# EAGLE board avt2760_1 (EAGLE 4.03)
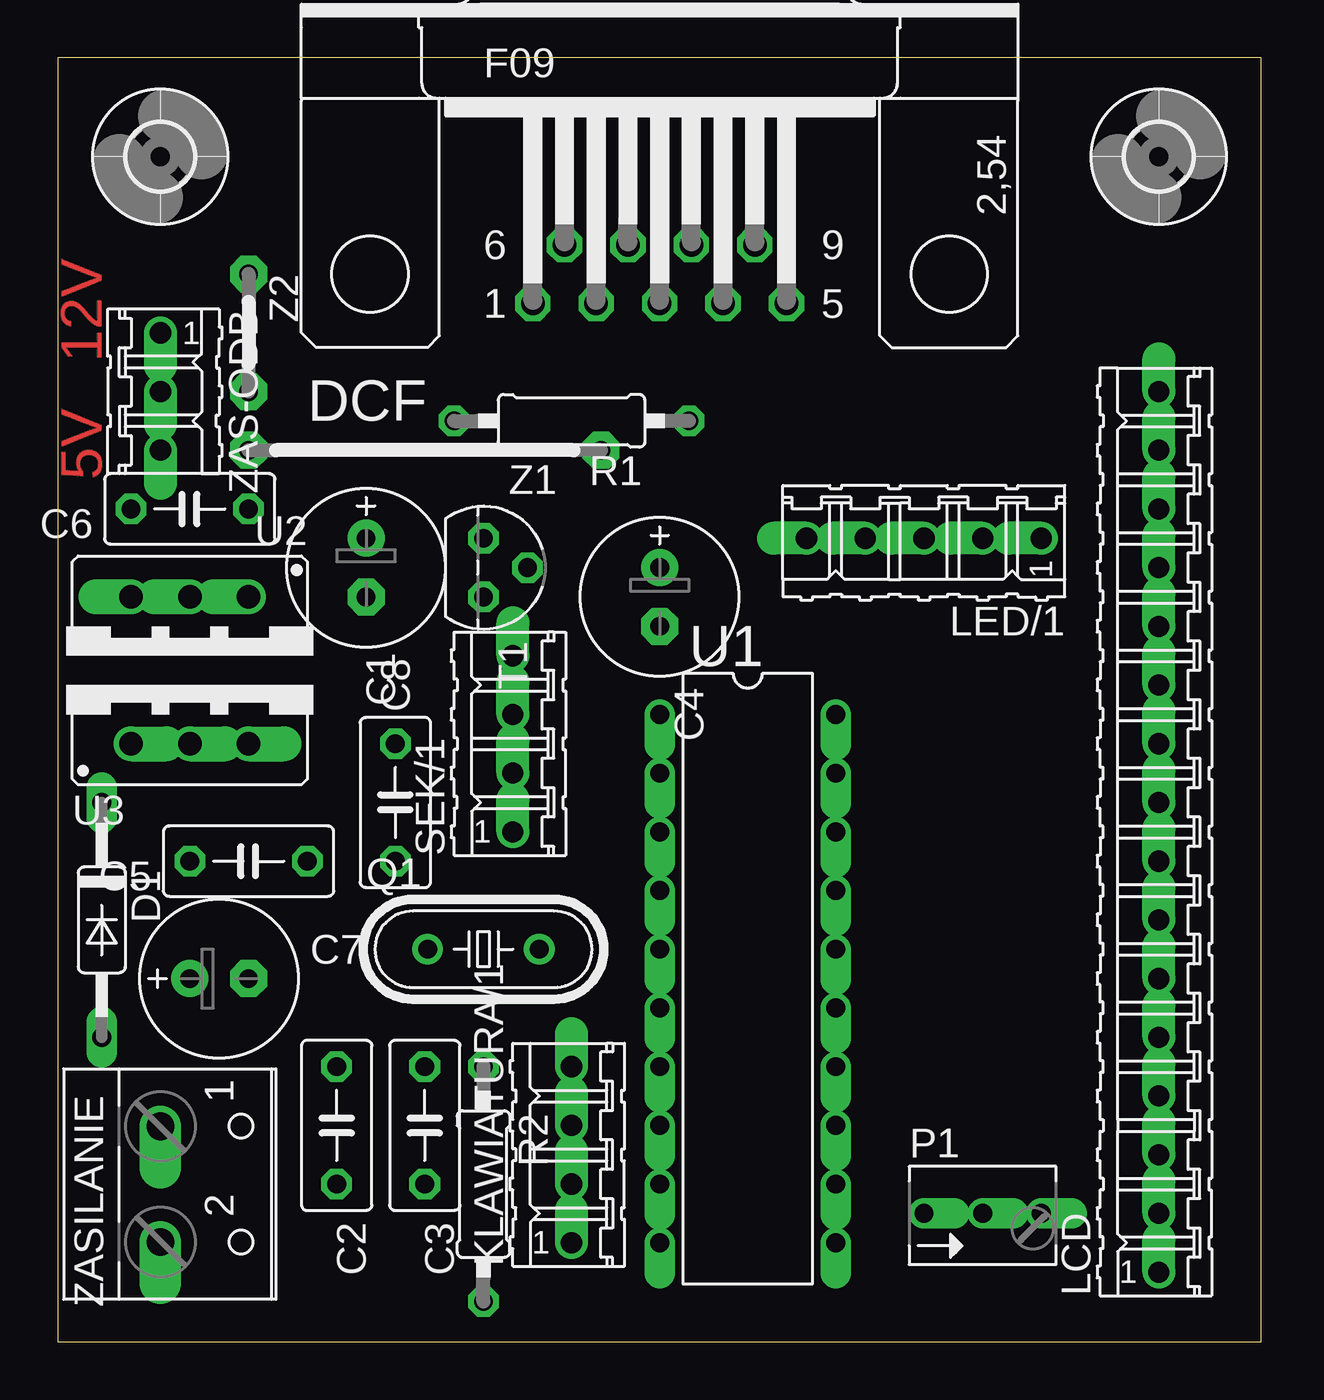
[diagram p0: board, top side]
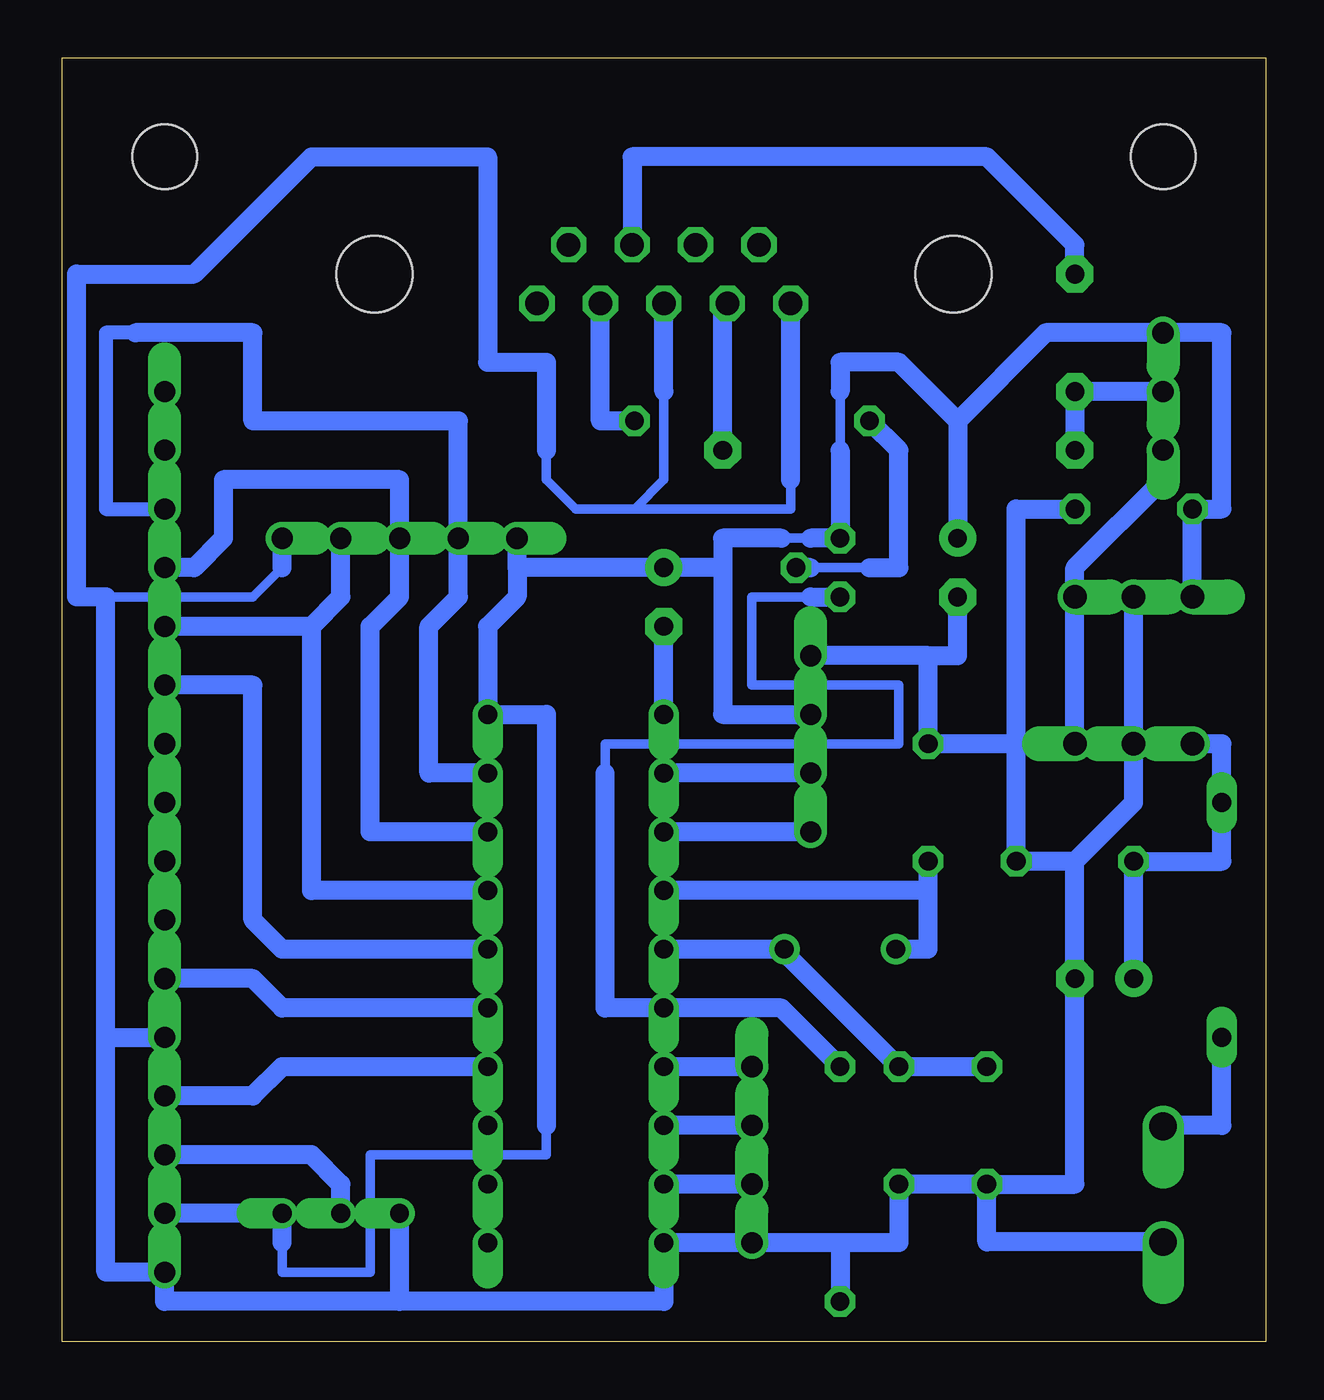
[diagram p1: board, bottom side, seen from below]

Size 52.05 x 55.55 mm. Coordinates in mm from the lower left corner, seen from the top.
Outline: 0,0 52.05,0 52.05,55.55 0,55.55 0,0
Copper layers used: Bottom

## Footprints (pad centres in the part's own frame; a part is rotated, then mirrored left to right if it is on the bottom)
C050-030X075 = drill 0.813 octagon: 1 -2.54,0; 2 2.54,0
E2,5-7 = drill 0.813 pad 1.6 round: + -1.27,0 | drill 0.813 pad 1.6 octagon: - 1.27,0
DO35-10 = drill 0.813 long: A 5.08,0; C -5.08,0
F09H = drill 1.016 octagon: 1 -5.486,-1.27; 2 -2.743,-1.27; 3 0,-1.27; 4 2.743,-1.27; 5 5.486,-1.27; 6 -4.115,1.27; 7 -1.372,1.27; 8 1.372,1.27; 9 4.115,1.27 | hole 3.302: -12.522,0; 12.522,0
04P = drill 0.914 offset: 1 -3.81,0; 2 -1.27,0; 3 1.27,0; 4 3.81,0
16P = drill 0.914 offset: 1 -19.05,0; 2 -16.51,0; 3 -13.97,0; 4 -11.43,0; 5 -8.89,0; 6 -6.35,0; 7 -3.81,0; 8 -1.27,0; 9 1.27,0; 10 3.81,0; 11 6.35,0; 12 8.89,0; 13 11.43,0; 14 13.97,0; 15 16.51,0; 16 19.05,0
05P = drill 0.914 offset: 1 -5.08,0; 2 -2.54,0; 3 0,0; 4 2.54,0; 5 5.08,0
B64Y = drill 0.813 offset: 1 2.54,0; 2 0,0; 3 -2.54,0
HC49/S = drill 0.813 round: 1 -2.413,0; 2 2.413,0
0207/10 = drill 0.813 octagon: 1 -5.08,0; 2 5.08,0
TO92 = drill 0.813 octagon: 1 1.27,0; 2 0,1.905; 3 -1.27,0
DIL20 = drill 0.813 offset: 1 -11.43,-3.81; 2 -8.89,-3.81; 3 -6.35,-3.81; 4 -3.81,-3.81; 5 -1.27,-3.81; 6 1.27,-3.81; 7 3.81,-3.81; 8 6.35,-3.81; 9 8.89,-3.81; 10 11.43,-3.81; 11 11.43,3.81; 12 8.89,3.81; 13 6.35,3.81; 14 3.81,3.81; 15 1.27,3.81; 16 -1.27,3.81; 17 -3.81,3.81; 18 -6.35,3.81; 19 -8.89,3.81; 20 -11.43,3.81
78XXS = drill 1.016 offset: GND 0,-2.54; IN -2.54,-2.54; OUT 2.54,-2.54
2,8 = hole 2.8: 0,0
15 = drill 0.813 pad 1.6 octagon: 1 -7.62,0; 2 7.62,0
05 = drill 0.813 pad 1.6 octagon: 1 -2.54,0; 2 2.54,0
03P = drill 0.914 offset: 1 -2.54,0; 2 0,0; 3 2.54,0
W237-102 = drill 1.194 offset: 1 -2.5,-1.27; 2 2.5,-1.27

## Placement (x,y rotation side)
C1  27p  [C050-030X075]  14.6,23.33 90 top
C2  27p  [C050-030X075]  12.06,9.36 270 top
C3  [C050-030X075]  15.87,9.36 270 top
C4  1u  [E2,5-7]  26.03,32.22 270 top
C5  100n  [C050-030X075]  8.25,20.79 180 top
C6  100n  [C050-030X075]  5.71,36.03 180 top
C7  200u  [E2,5-7]  6.98,15.71 0 top
C8  100u  [E2,5-7]  13.33,33.49 270 top
D1  1N4148  [DO35-10]  1.9,18.25 270 top
DCF  [F09H]  26.03,46.19 0 top
KLAWIATURA/1  [04P]  22.22,8.09 90 top
LCD  [16P]  47.62,22.06 90 top
LED/1  [05P]  37.46,34.76 180 top
P1  50K  [B64Y]  40,5.55 0 top
Q1  [HC49/S]  18.41,16.98 0 top
R1  1K  [0207/10]  22.22,39.84 180 top
R2  1K  [0207/10]  18.41,6.82 270 top
SEK/1  [04P]  19.68,25.87 90 top
T1  BC547  [TO92]  18.41,33.49 270 top
U1  AT89C4051  [DIL20]  29.84,15.71 270 top
U2  7805  [78XXS]  5.71,29.68 180 top
U3  7812  [78XXS]  5.71,28.41 0 top
U$1  [2,8]  4.44,51.27 0 top
U$2  [2,8]  47.62,51.27 0 top
Z1  [15]  15.87,38.57 180 top
Z2  [05]  8.25,43.65 270 top
ZAS-ODB  [03P]  4.44,41.11 270 top
ZASILANIE  [W237-102]  5.71,6.82 270 top

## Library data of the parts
C1-C8 R1 R2 = rcl
D1 = diode
DCF = con-subd
KLAWIATURA/1 LCD LED/1 SEK/1 ZAS-ODB = con-amp-quick
P1 = pot
Q1 = crystal
T1 = transistor-npn
U1 = atmel
U2 U3 = v-reg
U$1 U$2 = holes
Z1 Z2 = jumper
ZASILANIE = con-wago-500

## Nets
+5V: C4.+ C6.2 C8.+ LCD.2 LED/1.5 P1.1 SEK/1.3 T1.3 U1.20 U2.OUT ZAS-ODB.1
+12V: U2.IN U3.OUT ZAS-ODB.3
GND: C1.2 C2.2 C3.2 C5.1 C6.1 C7.- C8.- DCF.1 DCF.3 KLAWIATURA/1.1 LCD.1 LCD.5 LED/1.1 P1.3 R2.2 SEK/1.4 U1.10 U2.GND U3.GND ZASILANIE.2
N$1: C2.1 C3.1 Q1.2 U1.5
N$2: C1.1 Q1.1 U1.4
N$3: C4.- U1.1
N$4: LCD.6 U1.15
N$5: LCD.4 U1.14
N$6: R1.2 T1.2
N$7: LCD.3 P1.2
N$8: R2.1 T1.1 U1.6
N$9: LCD.11 U1.16
N$10: LCD.12 LED/1.2 U1.17
N$11: LCD.13 LED/1.3 U1.18
N$12: LCD.14 LED/1.4 U1.19
N$13: DCF.4 R1.1
N$14: Z1.2 Z2.2 ZAS-ODB.2
N$15: KLAWIATURA/1.2 U1.9
N$16: KLAWIATURA/1.3 U1.8
N$17: D1.A ZASILANIE.1
N$18: C5.2 C7.+ D1.C U3.IN
N$19: KLAWIATURA/1.4 U1.7
N$20: SEK/1.1 U1.3
N$21: SEK/1.2 U1.2
N$22: DCF.2 Z1.1
N$23: DCF.8 Z2.1

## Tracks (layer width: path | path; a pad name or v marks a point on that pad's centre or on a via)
+5V
  Bottom 0.406: 31.11,9.36 31.11,8.09 38.73,8.09 38.73,3.01 42.54,3.01 42.54,4.28 | 19.68,34.76 20.95,34.76 | 18.41,41.11 18.41,38.57
  Bottom 0.813: LCD.2 P1.1 42.54,4.28 | 32.38,33.49 32.38,32.22 33.65,30.95 U1.20 31.11,27.14 31.11,9.36 | 32.38,33.49 LED/1.5 | SEK/1.3 23.49,27.14 23.49,33.49 | 23.49,33.49 23.49,34.76 20.95,34.76 | 1.9,43.65 1.9,36.03 C6.2 U2.OUT | 1.9,43.65 9.52,43.65 13.33,39.84 | 1.9,43.65 ZAS-ODB.1 | 19.68,34.76 T1.3 18.41,38.57 | 23.49,33.49 C4.+ 32.38,33.49 | 13.33,39.84 15.87,42.38 18.41,42.38 18.41,41.11 | 13.33,39.84 C8.+
+12V
  Bottom 0.813: U3.OUT U2.IN 8.25,33.49 4.44,37.3 ZAS-ODB.3
GND
  Bottom 0.406: 42.54,33.49 43.81,32.22 50.16,32.22 | 31.11,38.57 31.11,37.3 29.84,36.03 27.3,36.03 | 27.3,36.03 26.03,37.3 26.03,41.11 | 20.54,37.3 20.54,36.03 27.3,36.03
  Bottom 0.813: ZASILANIE.2 12.06,4.32 C2.2 | C2.2 C3.2 15.87,4.28 18.41,4.28 | 18.41,4.28 KLAWIATURA/1.1 U1.10 26.03,1.74 37.46,1.74 | 37.46,1.74 47.62,1.74 LCD.1 50.16,3.01 50.16,13.17 | C2.2 8.25,6.82 C7.- 8.25,20.79 | 8.25,20.79 C5.1 10.79,25.87 | 10.79,25.87 C1.2 14.6,29.68 | 37.46,1.74 P1.3 | 50.16,13.17 50.16,32.22 51.43,32.22 51.43,46.19 46.35,46.19 41.27,51.27 33.65,51.27 33.65,42.38 31.11,42.38 31.11,38.57 | 50.16,13.17 LCD.5 | 42.54,33.49 LED/1.1 | 14.6,29.68 SEK/1.4 | U2.GND U3.GND 5.71,23.33 8.25,20.79 | C6.1 10.79,36.03 10.79,25.87 | 18.41,4.28 R2.2 | 26.03,41.11 DCF.3 | 20.54,37.3 DCF.1 | C8.- 13.33,29.68 14.6,29.68
N$1
  Bottom 0.813: C2.1 C3.1 20.95,16.98 | 20.95,16.98 Q1.2 | 20.95,16.98 U1.5
N$2
  Bottom 0.813: 14.6,19.52 C1.1 | 14.6,19.52 14.6,16.98 Q1.1 | 14.6,19.52 U1.4
N$3
  Bottom 0.813: U1.1 C4.-
N$4
  Bottom 0.813: U1.15 42.54,14.44 43.81,15.71 LCD.6
N$5
  Bottom 0.813: U1.14 42.54,11.9 43.81,10.63 LCD.4
N$6
  Bottom 0.406: 17.14,33.49 19.68,33.49
  Bottom 0.813: R1.2 15.87,38.57 15.87,33.49 17.14,33.49 | 19.68,33.49 T1.2
N$7
  Bottom 0.813: P1.2 40,6.82 41.27,8.09 LCD.3
N$8
  Bottom 0.406: 28.57,24.6 28.57,25.87 15.87,25.87 15.87,28.41 22.22,28.41 22.22,32.22 19.68,32.22
  Bottom 0.813: R2.1 20.95,14.44 U1.6 28.57,14.44 28.57,24.6 | 19.68,32.22 T1.1
N$9
  Bottom 0.813: U1.16 42.54,16.98 43.81,18.25 43.81,28.41 LCD.11
N$10
  Bottom 0.813: U1.17 41.27,19.52 41.27,30.95 | 41.27,30.95 40,32.22 LED/1.2 | 41.27,30.95 LCD.12
N$11
  Bottom 0.813: U1.18 38.73,22.06 38.73,30.95 37.46,32.22 LED/1.3 37.46,37.3 45.08,37.3 45.08,34.76 46.35,33.49 LCD.13
N$12
  Bottom 0.61: LCD.14 50.16,36.03 50.16,43.65 48.89,43.65
  Bottom 0.813: U1.19 36.19,24.6 36.19,30.95 34.92,32.22 LED/1.4 34.92,39.84 43.81,39.84 43.81,43.65 48.89,43.65
N$13
  Bottom 0.813: DCF.4 28.77,39.84 R1.1
N$14
  Bottom 0.813: Z1.2 Z2.2 ZAS-ODB.2
N$15
  Bottom 0.813: KLAWIATURA/1.2 U1.9
N$16
  Bottom 0.813: KLAWIATURA/1.3 U1.8
N$17
  Bottom 0.813: ZASILANIE.1 4.44,9.36 1.9,9.36 D1.A
N$18
  Bottom 0.813: C7.+ C5.2 1.9,20.79 D1.C 1.9,25.87 U3.IN
N$19
  Bottom 0.813: KLAWIATURA/1.4 U1.7
N$20
  Bottom 0.813: SEK/1.1 U1.3
N$21
  Bottom 0.813: SEK/1.2 U1.2
N$22
  Bottom 0.813: DCF.2 23.49,44.72 Z1.1
N$23
  Bottom 0.813: Z2.1 8.25,47.46 12.06,51.27 27.4,51.27 DCF.8

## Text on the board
Top: 12V | 5V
